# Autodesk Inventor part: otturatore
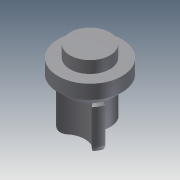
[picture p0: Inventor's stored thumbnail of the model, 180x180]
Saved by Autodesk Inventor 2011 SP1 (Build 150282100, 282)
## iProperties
Created: 2014-01
Part Number: otturatore
Document SubType Name: Modeling
Designer: UTENTE
Density: 1 g/cm^3
Author: UTENTE
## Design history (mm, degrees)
sketch "Schizzo1"
  geometry: C1 r 6 at (0, 0); 1 further point
  constraints: 1 centre point, 1 coincident
extrude "Estrusione1" new body sketch "Schizzo1" distance "d1" = 11; taper "d2" = 0 deg
chamfer "Smusso1" distance "d3" = 0.5; stored, may be unused: second distance "d4" = 2, angle "d5" = 45 deg
sketch "Schizzo2"
  geometry: C1 r 5.5 at (0, 0) reference; C2 r 8 at (0, 0)
  constraints: 1 centre point, 1 coincident
extrude "Estrusione2" join sketch "Schizzo2" distance "d7" = 6; taper "d8" = 0 deg
sketch "Schizzo3"
  geometry: C1 r 8 at (0, 0) reference; C2 r 5 at (0, 0)
  constraints: 1 centre point, 1 coincident
extrude "Estrusione3" join sketch "Schizzo3" distance "d10" = 3; taper "d11" = 0 deg
fillet "Raccordo1" dims "d12" = 2
sketch "Schizzo4"
  geometry: L1 (-5.5, 11)-(-8, 11) reference; L2 (-8, 11)-(-8, 17) reference; L3 (-8, 17)-(-5, 17) reference; L4 (-5, 17)-(-5, 20) reference; L5 (-5, 20)-(5, 20) reference; L6 (5, 20)-(5, 17) reference; L7 (5, 17)-(8, 17) reference; L8 (8, 17)-(8, 11) reference; L9 (8, 11)-(5.5, 11) reference; L10 (5.5, 11)-(6, 10.5) reference; L11 (6, 10.5)-(6, 2) reference; L12 (4, 0)-(-4, 0) reference; L13 (-6, 2)-(-6, 10.5) reference; L14 (-6, 10.5)-(-5.5, 11) reference; L15 (-5.5, 11)-(-10.468, 15.968); L16 (-10.468, 15.968)-(-10.468, 11); L17 (-10.468, 11)-(-5.5, 11); L18 (0, -4.497)-(0, 24.083) reference; A1 r 2 centre (4, 2) between (4, 0) and (6, 2) reference; A2 r 2 centre (-4, 2) between (-6, 2) and (-4, 0) reference; 1 further point
  constraints: 6 end point, 2 perpendicular, 1 parallel
revolve "Rivoluzione1" sketch "Schizzo4" stored, may be unused: angle "d13" = 90 deg
sketch "Schizzo5"
  geometry: C1 r 5 at (-5.441, 3.141); C2 r 5 at (0, -6.283); C3 r 5 at (5.441, 3.141); 1 further point
  constraints: 3 centre point, 7 other
  dimensions: "d25" = 360 deg dimension on point (0, 0) C1.centre (derived)
extrude "Estrusione4" cut sketch "Schizzo5" distance "d27" = 11; taper "d28" = 0 deg
node "Solido1"
node "Proietta spigoli di taglio1"
